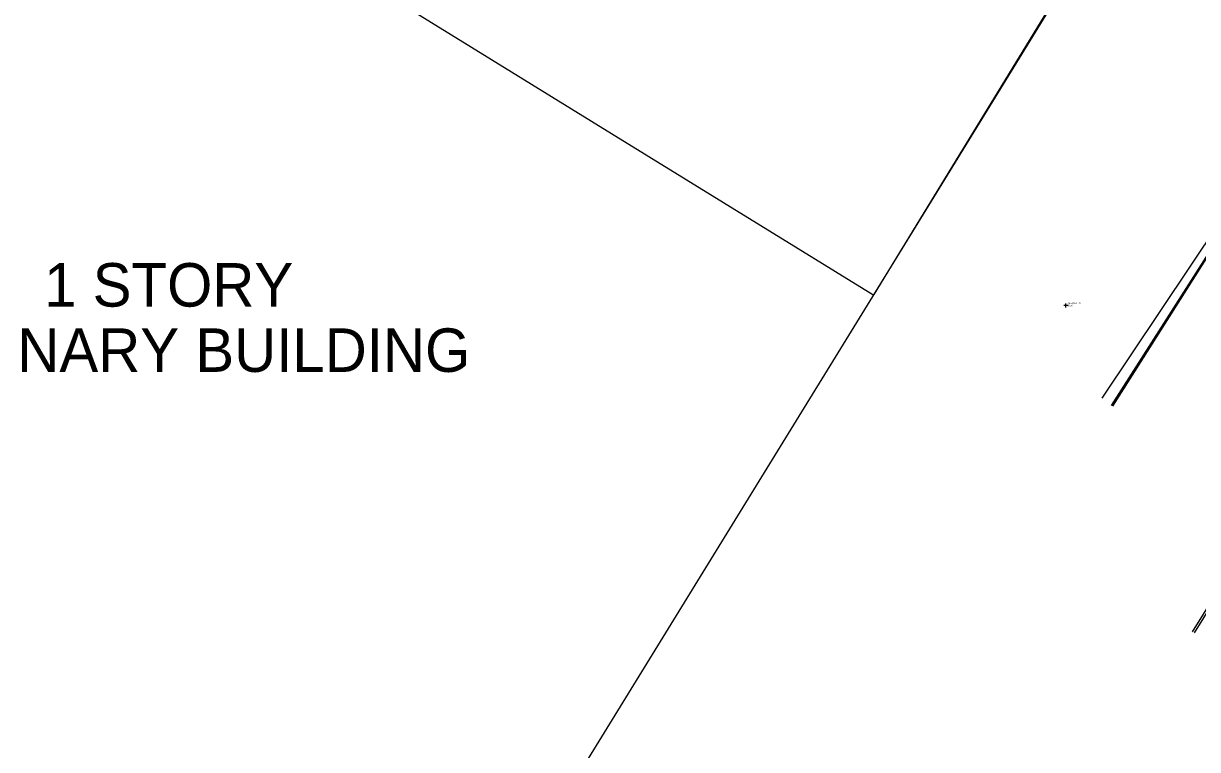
# Model space of a CAD drawing. Extents: x 509744 to 512285, y 1314862 to 1316822.
# Drawn here: x 510479.2 to 510554.7, y 1315294.3 to 1315341 of the extents above; entities that cross this region are included whole.
import ezdxf

# ---------------------------------------------------------------- set-up
doc = ezdxf.new("R2010")
doc.units = 0
for name, color, linetype in [('Building_ep', 7, 'Continuous'), ('CGBack_ep', 7, 'Continuous'), ('CGFace_ep', 7, 'Continuous'), ('Driveway_ep', 7, 'Continuous'), ('Fence_ep', 7, 'Continuous'), ('GroundShot_ep', 7, 'Continuous'), ('LARWLine_ep', 7, 'Continuous'), ('TextElevLabel', 7, 'Continuous'), ('TextPtLabel', 7, 'Continuous'), ('TextTopoLabel_ep', 7, 'Continuous')]:
    doc.layers.add(name, color=color, linetype=linetype)

msp = doc.modelspace()

# ---------------------------------------------------------------- linework, layer by layer
at = {"layer": 'Building_ep'}
msp.add_lwpolyline([(510444.29, 1315321.724), (510469.732, 1315363.166), (510517.064, 1315333.974), (510533.864, 1315323.605)], dxfattribs=at)
at = {"layer": 'CGBack_ep'}
msp.add_line((510548.625, 1315316.952), (510556.156, 1315328.232), dxfattribs=at)
at = {"layer": 'CGFace_ep'}
for p, q in [((510549.219, 1315316.481), (510556.494, 1315327.905)), ((510565.493, 1315319.598), (510554.528, 1315301.842))]:
    msp.add_line(p, q, dxfattribs=at)
at = {"layer": 'Driveway_ep'}
for p, q in [((510549.296, 1315316.421), (510556.539, 1315327.862)), ((510554.434, 1315301.91), (510565.37, 1315319.677))]:
    msp.add_line(p, q, dxfattribs=at)
at = {"layer": 'Fence_ep'}
msp.add_lwpolyline([(510528.606, 1315372.842), (510534.959, 1315382.841), (510548.115, 1315375.142), (510554.673, 1315357.576), (510533.932, 1315323.607)], dxfattribs=at)
at = {"layer": 'GroundShot_ep'}
for p, q in [((510546.407, 1315322.909), (510546.157, 1315322.909)), ((510546.282, 1315322.784), (510546.282, 1315323.034))]:
    msp.add_line(p, q, dxfattribs=at)
at = {"layer": 'LARWLine_ep'}
msp.add_line((510414.955, 1315130.239), (510554.464, 1315356.975), dxfattribs=at)

# ---------------------------------------------------------------- texts
at = {"layer": 'TextElevLabel'}
msp.add_text('19.86', height=0.1, dxfattribs=at).set_placement((510546.382, 1315322.859))
at = {"layer": 'TextPtLabel'}
msp.add_text('DEFAULT_70', height=0.1, dxfattribs=at).set_placement((510546.382, 1315323.009))
at = {"layer": 'TextTopoLabel_ep'}
for s, p in [('1 STORY ', (510480.573, 1315322.832)), ('MASONARY BUILDING', (510467.826, 1315318.632))]:
    msp.add_text(s, height=2.8, dxfattribs=at).set_placement(p)

doc.saveas('drawing.dxf')
